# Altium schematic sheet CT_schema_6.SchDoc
size 368 x 333 mm
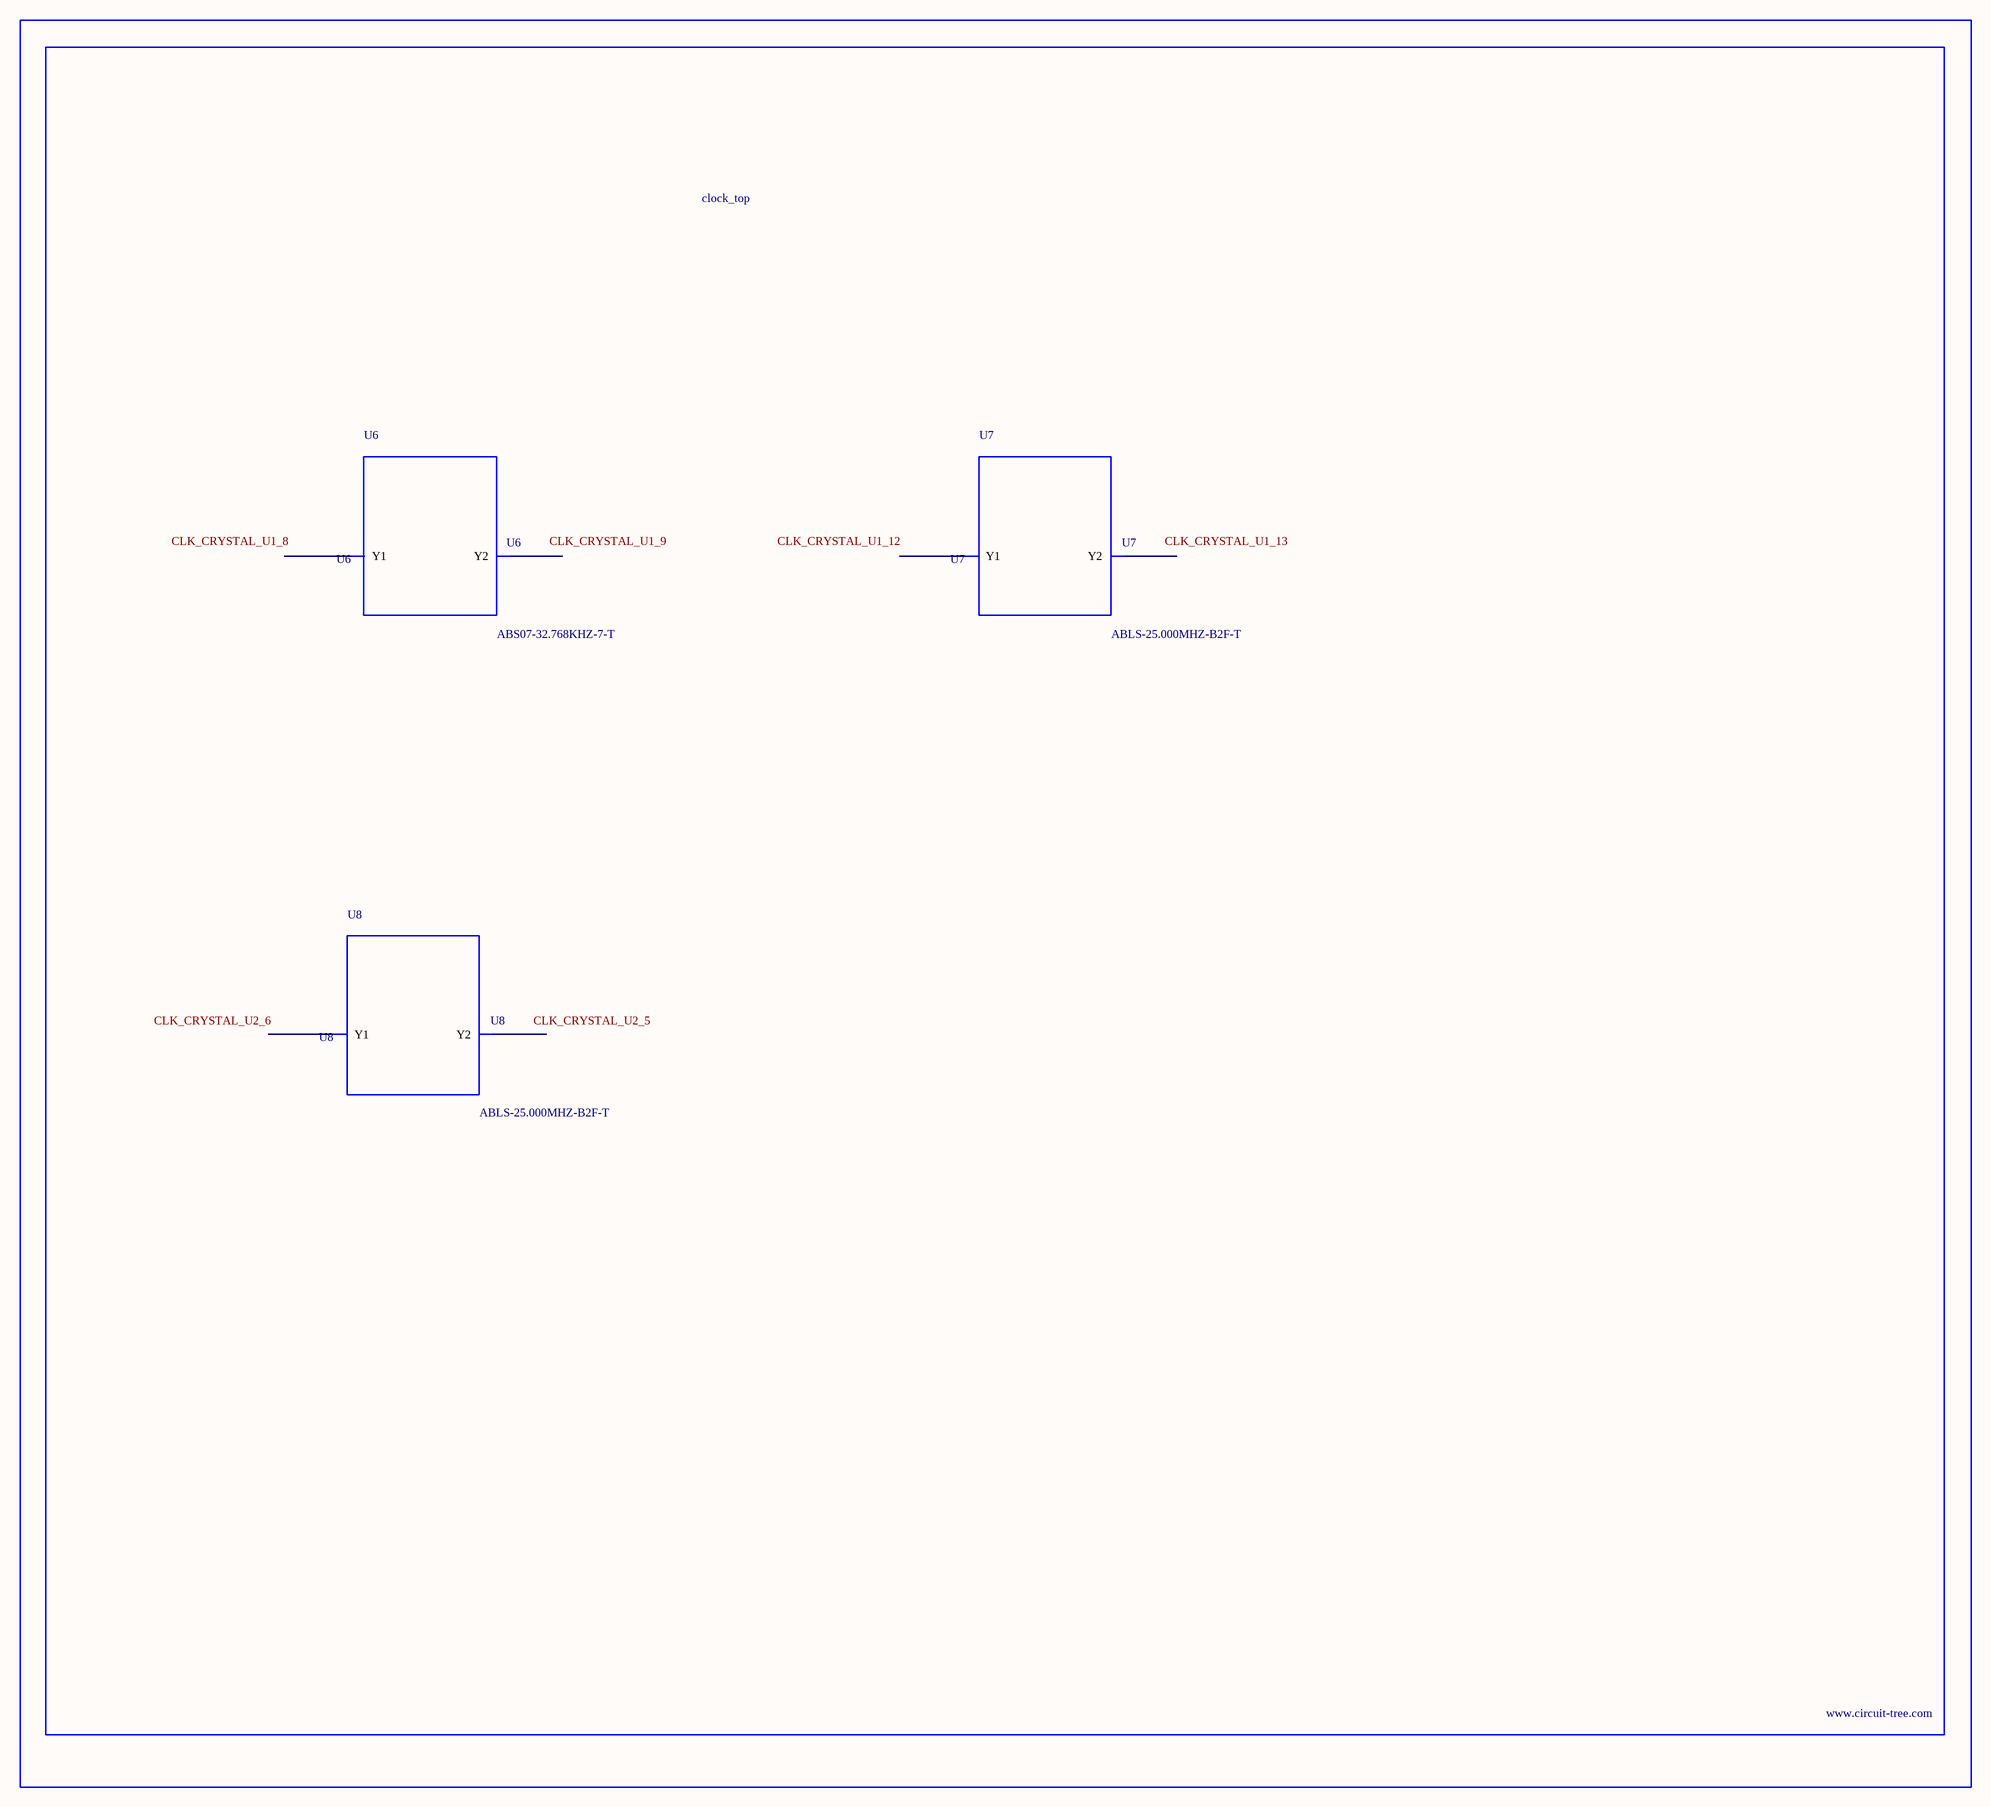
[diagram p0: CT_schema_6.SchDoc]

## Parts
BORDER5  (no value)
U6  ABS07-32.768KHZ-7-T  [ABS07-32.768KHZ-7-T]
U7  ABLS-25.000MHZ-B2F-T  [ABLS-25.000MHZ-B2F-T]
U8  ABLS-25.000MHZ-B2F-T  [ABLS-25.000MHZ-B2F-T]

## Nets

Not connected (* = marked no-connect by the designer): U6 1(Y1) 2(Y2); U7 1(Y1) 2(Y2); U8 1(Y1) 2(Y2)

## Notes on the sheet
- Labels drawn without touching a wire or pin: CLK_CRYSTAL_U1_8, CLK_CRYSTAL_U1_9, CLK_CRYSTAL_U1_12, CLK_CRYSTAL_U1_13, CLK_CRYSTAL_U2_5, CLK_CRYSTAL_U2_6

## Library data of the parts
BORDER5 = BORDER_PAGE5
